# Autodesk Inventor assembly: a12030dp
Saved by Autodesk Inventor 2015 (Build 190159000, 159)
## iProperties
Created: 2022-06
Part Number: a12030dp
Checked By: TraceParts S.A.
Catalog Web Link: www.traceparts.com
Document SubType Name: Assembly
Designer: TraceParts
Company: TraceParts S.A.
Author: TraceParts
DESIGN: NITRA pneumatic cylinder, non-repairable, 3/4in bore, 1/4in rod diameter, 3in stroke, double acting, rear pivot mount.
Part_Number_EShop_URL: http://www.adcpn.com/pn/A12030DP
SUPPLIER_PART_NUMBER: A12030DP
SUPPLIER_NAME: AutomationDirect
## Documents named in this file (4)
- C:\Program Files (x86)\Trace Software\PartsXML Tools\RobotPartsAuto\AUTOMATION_DIRECT\CAD\Temp\a12030dp.iam
- C:\Program Files (x86)\Trace Software\PartsXML Tools\RobotPartsAuto\AUTOMATION_DIRECT\CAD\Temp\a12030dp_01.ipt
- C:\Program Files (x86)\Trace Software\PartsXML Tools\RobotPartsAuto\AUTOMATION_DIRECT\CAD\Temp\a12030dp_02.ipt
- C:\Program Files (x86)\Trace Software\PartsXML Tools\RobotPartsAuto\AUTOMATION_DIRECT\CAD\Temp\a12030dp_03.ipt
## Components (3 placed, 3 different names)
1. a12030dp_01:1
2. a12030dp_02:1
3. a12030dp_03:1
